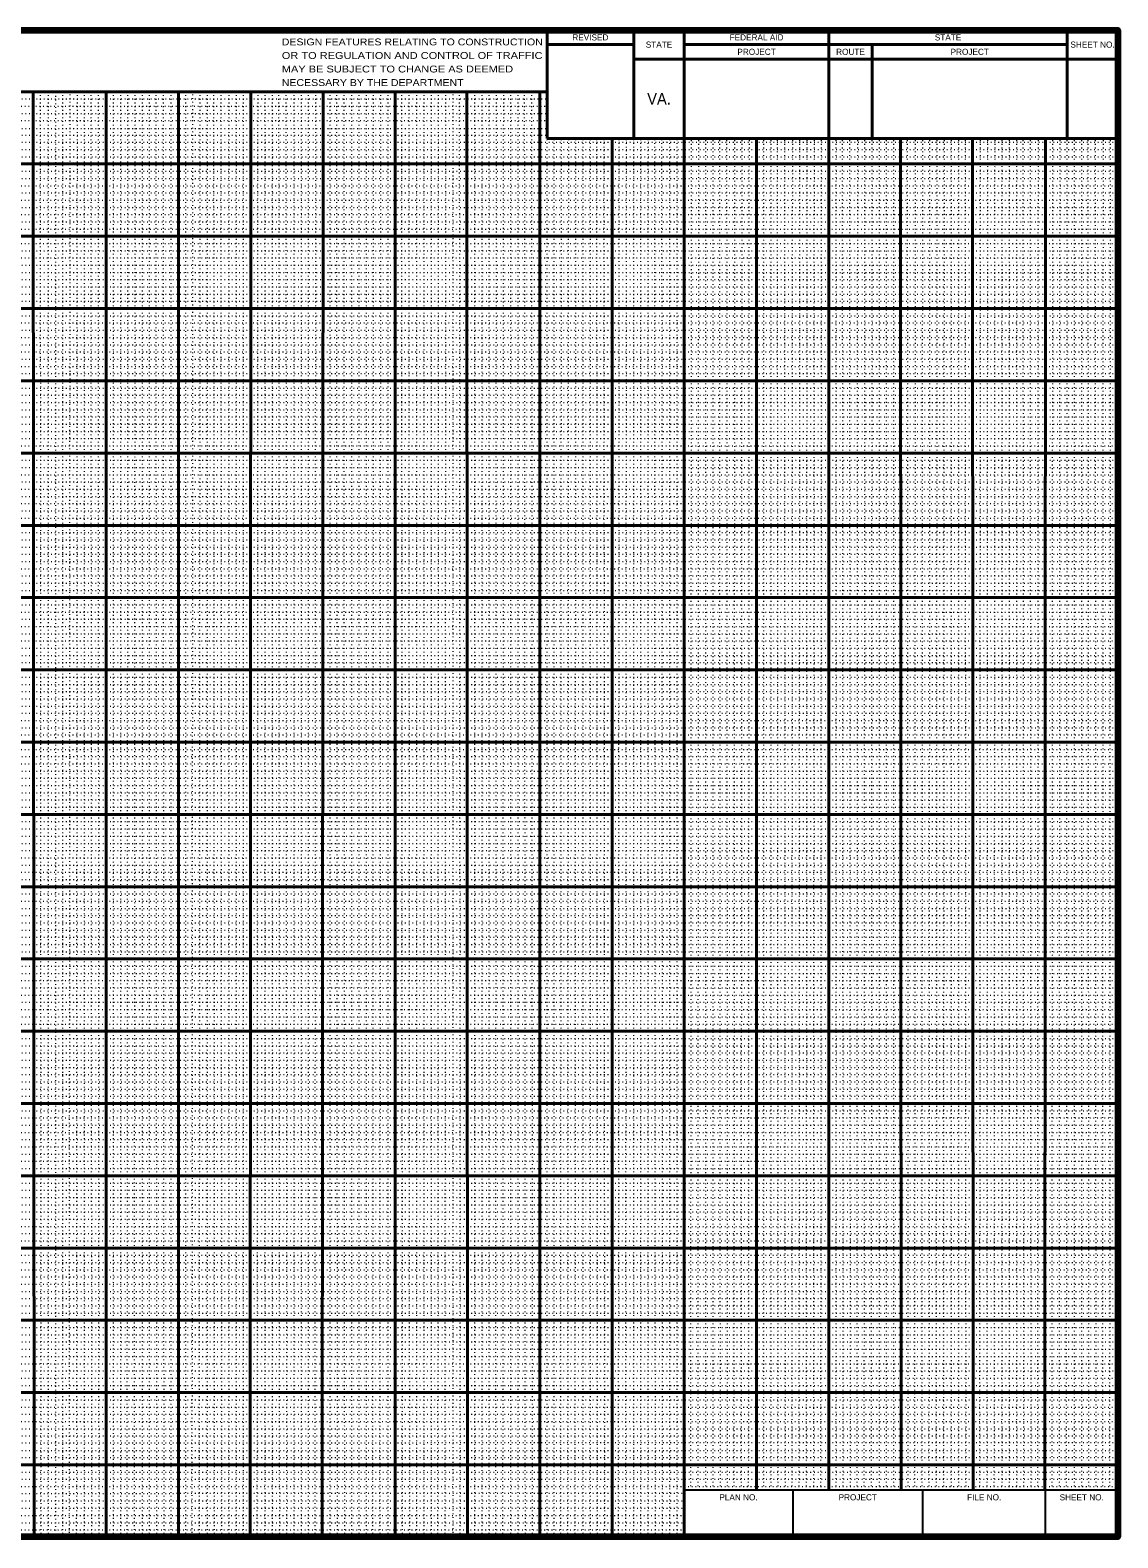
# Model space of a CAD drawing. Extents: x 224728 to 225078, y 224738 to 270738.
# Drawn here: x 224917.8 to 225068.4, y 241768.3 to 241976.9 of the extents above; entities that cross this region are included whole.
import ezdxf
from ezdxf.enums import TextEntityAlignment as Align

# ---------------------------------------------------------------- set-up
doc = ezdxf.new("R2010")
doc.units = 0
doc.header["$LTSCALE"] = 0.34
doc.linetypes.add('DOTTED', pattern=[1.5, 0.3, -1.2])
for name, color, linetype, lineweight in [('59', 7, 'DOTTED', 13), ('60', 7, 'Continuous', 40), ('61', 7, 'Continuous', 40)]:
    doc.layers.add(name, color=color, linetype=linetype, lineweight=lineweight)

msp = doc.modelspace()

# ---------------------------------------------------------------- linework, layer by layer
at = {"layer": '59'}
for p, q in [((224919.3649, 241768.3648), (224919.2649, 241968.3648)), ((224920.3649, 241768.3648), (224920.3649, 241968.3648)), ((224921.3649, 241768.2648), (224921.3649, 241968.3648)), ((224922.3649, 241768.3648), (224922.3649, 241968.3648)), ((224923.2649, 241768.4648), (224923.3649, 241968.3648)), ((224924.2649, 241768.3648), (224924.3649, 241968.3648)), ((224925.3649, 241768.3648), (224925.3649, 241968.3648)), ((224926.3649, 241768.3648), (224926.2649, 241968.3648)), ((224927.3649, 241768.3648), (224927.2649, 241968.3648)), ((224929.3649, 241768.3648), (224929.3649, 241968.3648)), ((224930.3649, 241768.3648), (224930.3649, 241968.3648)), ((224931.2649, 241768.3648), (224931.3649, 241968.3648)), ((224932.2649, 241768.3648), (224932.3649, 241968.3648)), ((224933.3649, 241768.3648), (224933.3649, 241968.3648)), ((224934.3649, 241768.3648), (224934.3649, 241968.3648)), ((224935.3649, 241768.3648), (224935.2649, 241968.3648)), ((224936.3649, 241768.3648), (224936.2649, 241968.3648)), ((224937.3649, 241768.3648), (224937.3649, 241968.3648)), ((224939.3649, 241768.3648), (224939.3649, 241968.4648)), ((224940.2649, 241768.4648), (224940.3649, 241968.3648)), ((224941.2649, 241768.3648), (224941.3649, 241968.3648)), ((224942.3649, 241768.3648), (224942.3649, 241968.3648)), ((224943.3649, 241768.3648), (224943.2649, 241968.3648)), ((224944.3649, 241768.3648), (224944.2649, 241968.3648)), ((224945.3649, 241768.3648), (224945.3649, 241968.3648)), ((224946.3649, 241768.3648), (224946.3649, 241968.3648)), ((224947.3649, 241768.3648), (224947.3649, 241968.3648)), ((224949.2649, 241768.3648), (224949.3649, 241968.3648)), ((224950.3649, 241768.3648), (224950.3649, 241968.3648)), ((224951.3649, 241768.3648), (224951.3649, 241968.3648)), ((224952.3649, 241768.3648), (224952.2649, 241968.3648)), ((224953.3649, 241768.3648), (224953.2649, 241968.3648)), ((224954.3649, 241768.3648), (224954.3649, 241968.3648)), ((224955.3649, 241768.3648), (224955.3649, 241968.3648)), ((224956.3649, 241768.3648), (224956.3649, 241968.3648)), ((224957.2649, 241768.3648), (224957.3649, 241968.3648)), ((224959.3649, 241768.3648), (224959.3649, 241968.3648)), ((224960.3649, 241768.3648), (224960.2649, 241968.3648)), ((224961.3649, 241768.3648), (224961.2649, 241968.3648)), ((224962.3649, 241768.3648), (224962.3649, 241968.3648)), ((224963.3649, 241768.3648), (224963.3649, 241968.3648)), ((224964.3649, 241768.3648), (224964.3649, 241968.3648)), ((224965.2649, 241768.3648), (224965.3649, 241968.3648)), ((224966.2649, 241768.3648), (224966.3649, 241968.3648)), ((224967.3649, 241768.3648), (224967.3649, 241968.3648)), ((224969.3649, 241768.3648), (224969.2649, 241968.3648)), ((224970.3649, 241768.3648), (224970.2649, 241968.3648)), ((224971.3649, 241768.3648), (224971.3649, 241968.3648)), ((224972.3649, 241768.3648), (224972.3649, 241968.3648)), ((224973.3649, 241768.3648), (224973.3649, 241968.3648)), ((224974.2649, 241768.3648), (224974.3649, 241968.3648)), ((224975.2649, 241768.3648), (224975.3649, 241968.3648)), ((224976.3649, 241768.4648), (224976.3649, 241968.3648)), ((224977.3649, 241768.3648), (224977.2649, 241968.4648)), ((224979.3649, 241768.3648), (224979.3649, 241968.3648)), ((224980.3649, 241768.3648), (224980.3649, 241968.3648)), ((224981.3649, 241768.3648), (224981.3649, 241968.3648)), ((224982.2649, 241768.3648), (224982.3649, 241968.3648)), ((224983.2649, 241768.3648), (224983.3649, 241968.3648)), ((224984.3649, 241768.3648), (224984.3649, 241968.3648)), ((224985.3649, 241768.3648), (224985.3649, 241968.3648)), ((224986.3649, 241768.3648), (224986.2649, 241968.3648)), ((224987.3649, 241768.3648), (224987.2649, 241968.3648)), ((224748.2649, 241966.3648), (224989.3649, 241966.3648)), ((224748.3649, 241967.3648), (224989.3649, 241967.3648)), ((224748.2649, 241964.3648), (224989.3649, 241964.3648)), ((224748.3649, 241965.3648), (224989.3649, 241965.3648)), ((224748.3649, 241963.3648), (224989.3649, 241963.2648)), ((224748.3649, 241962.3648), (224989.3649, 241962.3648)), ((224989.3649, 241768.3648), (224989.3649, 241961.8844)), ((224990.3649, 241768.3648), (224990.3649, 241961.8844)), ((224991.2649, 241768.3648), (224991.3647, 241961.8844)), ((224992.2649, 241768.3648), (224992.3647, 241961.8844)), ((224993.2649, 241768.3648), (224993.3647, 241961.8844)), ((224994.3649, 241768.3648), (224994.3649, 241961.8844)), ((224995.3649, 241768.3648), (224995.3649, 241961.8844)), ((224996.3649, 241768.3648), (224996.2651, 241961.8844)), ((224997.3649, 241768.3648), (224997.2651, 241961.8844)), ((224999.2649, 241768.3648), (224999.3647, 241961.8844)), ((225000.2649, 241768.3648), (225000.3647, 241961.8844)), ((225001.3649, 241768.3648), (225001.3649, 241961.8844)), ((225002.3649, 241768.3648), (225002.3649, 241961.8844)), ((225003.3649, 241768.3648), (225003.3649, 241961.8844)), ((225004.3649, 241768.3648), (225004.2652, 241961.8844)), ((225005.3649, 241768.3648), (225005.2651, 241961.8844)), ((225006.3649, 241768.3648), (225006.3649, 241961.8844)), ((225007.3649, 241768.3648), (225007.3649, 241961.8844)), ((225009.2683, 241774.885), (225009.3646, 241961.8845)), ((225010.2683, 241774.885), (225010.3646, 241961.8845)), ((225011.3648, 241774.885), (225011.3648, 241961.8845)), ((225012.3648, 241774.885), (225012.3648, 241961.8845)), ((225013.3614, 241774.885), (225013.2651, 241961.8845)), ((225014.3614, 241774.885), (225014.2651, 241961.8845)), ((225015.2683, 241774.885), (225015.3646, 241961.8845)), ((225016.2683, 241774.885), (225016.3646, 241961.8845)), ((225017.2683, 241774.885), (225017.3646, 241961.8845)), ((225019.3648, 241774.885), (225019.3648, 241961.8845)), ((225020.3648, 241774.885), (225020.3648, 241961.8845)), ((225021.3614, 241774.885), (225021.2651, 241961.8845)), ((225022.3614, 241774.885), (225022.2651, 241961.8845)), ((225023.2683, 241774.885), (225023.3646, 241961.8845)), ((225024.2683, 241774.885), (225024.3646, 241961.8845)), ((225025.2683, 241774.885), (225025.3646, 241961.8845)), ((225026.2683, 241774.885), (225026.3646, 241961.8845)), ((225027.2683, 241774.885), (225027.3646, 241961.8845)), ((225029.3648, 241774.885), (225029.3648, 241961.8845)), ((225030.3614, 241774.885), (225030.2651, 241961.8845)), ((225031.3614, 241774.885), (225031.2651, 241961.8845)), ((225032.2683, 241774.885), (225032.3646, 241961.8845)), ((225033.2683, 241774.885), (225033.3646, 241961.8845)), ((225034.2683, 241774.885), (225034.3646, 241961.8845)), ((225035.3648, 241774.885), (225035.3648, 241961.8846)), ((225036.3648, 241774.885), (225036.3648, 241961.8846)), ((225037.3648, 241774.885), (225037.3648, 241961.8846)), ((225039.3614, 241774.885), (225039.2651, 241961.8846)), ((225040.2682, 241774.885), (225040.3645, 241961.8846)), ((225041.2683, 241774.885), (225041.3646, 241961.8846)), ((225042.2683, 241774.885), (225042.3646, 241961.8846)), ((225043.2683, 241774.885), (225043.3646, 241961.8845)), ((225044.2683, 241774.885), (225044.3646, 241961.8845)), ((225045.3648, 241774.885), (225045.3648, 241961.8845)), ((225046.3648, 241774.885), (225046.3648, 241961.8845)), ((225047.3614, 241774.885), (225047.2651, 241961.8845)), ((225049.2683, 241774.885), (225049.3646, 241961.8845)), ((225050.2682, 241774.885), (225050.3646, 241961.8845)), ((225051.2683, 241774.885), (225051.3646, 241961.8845)), ((225052.3648, 241774.885), (225052.3648, 241961.8845)), ((225053.3648, 241774.885), (225053.3648, 241961.8845)), ((225054.3648, 241774.885), (225054.3648, 241961.8845)), ((225055.3614, 241774.885), (225055.2651, 241961.8845)), ((225056.3614, 241774.885), (225056.2651, 241961.8845)), ((225057.2682, 241774.885), (225057.3645, 241961.8845)), ((225059.2683, 241774.885), (225059.3646, 241961.8845)), ((225060.2683, 241774.885), (225060.3646, 241961.8845)), ((225061.2683, 241774.885), (225061.3646, 241961.8845)), ((225062.3648, 241774.885), (225062.3648, 241961.8845)), ((225063.3648, 241774.885), (225063.3648, 241961.8845)), ((225064.3614, 241774.885), (225064.2651, 241961.8845)), ((225065.3614, 241774.885), (225065.2651, 241961.8845)), ((225066.2683, 241774.885), (225066.3646, 241961.8845)), ((225067.2682, 241774.885), (225067.3646, 241961.8845)), ((224748.3649, 241961.3648), (225068.2649, 241961.3648)), ((224748.3649, 241960.3648), (225068.3649, 241960.3648)), ((224748.3649, 241959.3648), (225068.3649, 241959.3648)), ((224748.3649, 241957.3648), (225068.3649, 241957.3648)), ((224748.3649, 241956.3648), (225068.3649, 241956.3648)), ((224748.2649, 241955.3648), (225068.3649, 241955.3648)), ((224748.3649, 241954.3648), (225068.3649, 241954.3648)), ((224748.2649, 241953.3648), (225068.3649, 241953.3648)), ((224748.2649, 241951.3648), (225068.3649, 241951.3648)), ((224748.3649, 241952.3648), (225068.2649, 241952.3648)), ((224748.2649, 241949.3648), (225068.3649, 241949.3648)), ((224748.3649, 241950.3648), (225068.3649, 241950.3648)), ((224748.2649, 241947.3648), (225068.3649, 241947.3648)), ((224748.2649, 241945.3648), (225068.3649, 241945.3648)), ((224748.3649, 241946.3648), (225068.2649, 241946.3648)), ((224748.3649, 241944.3648), (225068.2649, 241944.3648)), ((224748.3649, 241943.3648), (225068.3649, 241943.3648)), ((224748.3649, 241942.3648), (225068.3649, 241942.3648)), ((224748.3649, 241941.3648), (225068.3649, 241941.3648)), ((224748.3649, 241940.3648), (225068.3649, 241940.3648)), ((224748.3649, 241939.3648), (225068.3649, 241939.3648)), ((224748.3649, 241937.3648), (225068.3649, 241937.3648)), ((224748.2649, 241936.3648), (225068.3649, 241936.3648)), ((224748.3649, 241935.3648), (225068.2649, 241935.3648)), ((224748.2649, 241934.3648), (225068.3649, 241934.3648)), ((224748.3649, 241933.3648), (225068.3649, 241933.3648)), ((224748.2649, 241932.3648), (225068.3649, 241932.3648)), ((224748.3649, 241931.3648), (225068.2649, 241931.3648)), ((224748.2649, 241930.3648), (225068.3649, 241930.3648)), ((224748.3649, 241929.3648), (225068.2649, 241929.3648)), ((224748.3649, 241927.3648), (225068.2649, 241927.3648)), ((224748.3649, 241926.3648), (225068.3649, 241926.3648)), ((224748.3649, 241925.3648), (225068.2649, 241925.3648)), ((224748.3649, 241924.3648), (225068.3649, 241924.3648)), ((224748.3649, 241923.3648), (225068.3649, 241923.3648)), ((224748.3649, 241922.3648), (225068.3649, 241922.3648)), ((224748.3649, 241921.3648), (225068.3649, 241921.3648)), ((224748.3649, 241920.3648), (225068.3649, 241920.3648)), ((224748.2649, 241919.3648), (225068.3649, 241919.3648)), ((224748.3649, 241917.3648), (225068.3649, 241917.3648)), ((224748.3649, 241916.3648), (225068.3649, 241916.3648)), ((224748.2649, 241915.3648), (225068.3649, 241915.3648)), ((224748.3649, 241914.3648), (225068.2649, 241914.3648)), ((224748.2649, 241913.3648), (225068.3649, 241913.3648)), ((224748.3649, 241912.3648), (225068.2649, 241912.3648)), ((224748.2649, 241911.3648), (225068.3649, 241911.3648)), ((224748.3649, 241910.3648), (225068.2649, 241910.3648)), ((224748.2649, 241909.3648), (225068.3649, 241909.3648)), ((224748.3649, 241907.3648), (225068.3649, 241907.3648)), ((224748.3649, 241906.3648), (225068.3649, 241906.3648)), ((224748.3649, 241905.3648), (225068.3649, 241905.3648)), ((224748.3649, 241904.3648), (225068.3649, 241904.3648)), ((224748.3649, 241903.3648), (225068.3649, 241903.3648)), ((224748.2649, 241902.3648), (225068.3649, 241902.3648)), ((224748.3649, 241901.3648), (225068.3649, 241901.3648)), ((224748.3649, 241900.3648), (225068.3649, 241900.3648)), ((224748.3649, 241899.3648), (225068.3649, 241899.3648)), ((224748.3649, 241897.3648), (225068.2649, 241897.3648)), ((224748.2649, 241896.3648), (225068.3649, 241896.3648)), ((224748.3649, 241895.3648), (225068.2649, 241895.3648)), ((224748.2649, 241894.3648), (225068.3649, 241894.3648)), ((224748.3649, 241893.3648), (225068.2649, 241893.3648)), ((224748.2649, 241892.3648), (225068.3649, 241892.3648)), ((224748.3649, 241891.3648), (225068.2649, 241891.3648)), ((224748.3649, 241890.3648), (225068.3649, 241890.3648)), ((224748.3649, 241889.3648), (225068.2649, 241889.3648)), ((224748.3649, 241887.3648), (225068.3649, 241887.3648)), ((224748.3649, 241886.3648), (225068.3649, 241886.3648)), ((224748.3649, 241885.3648), (225068.3649, 241885.3648)), ((224748.3649, 241884.3648), (225068.3649, 241884.3648)), ((224748.3649, 241883.3648), (225068.3649, 241883.3648)), ((224748.2649, 241881.3648), (225068.3649, 241881.3648)), ((224748.3649, 241882.3648), (225068.3649, 241882.3648)), ((224748.2649, 241879.3648), (225068.3649, 241879.3648)), ((224748.3649, 241880.3648), (225068.3649, 241880.3648)), ((224748.2649, 241877.3648), (225068.3649, 241877.3648)), ((224748.3649, 241876.3648), (225068.2649, 241876.3648)), ((224748.2649, 241875.3648), (225068.3649, 241875.3648)), ((224748.3649, 241874.3648), (225068.2649, 241874.3648)), ((224748.3649, 241873.3648), (225068.3649, 241873.3648)), ((224748.3649, 241872.3648), (225068.2649, 241872.3648)), ((224748.3649, 241871.3648), (225068.3649, 241871.3648)), ((224748.3649, 241870.3648), (225068.3649, 241870.3648)), ((224748.3649, 241869.3648), (225068.3649, 241869.3648)), ((224748.3649, 241867.3648), (225068.3649, 241867.3648)), ((224748.3649, 241866.3648), (225068.3649, 241866.3648)), ((224748.3649, 241865.3648), (225068.3649, 241865.3648)), ((224748.3649, 241864.3648), (225068.3649, 241864.3648)), ((224748.2649, 241862.3648), (225068.3649, 241862.3648)), ((224748.3649, 241863.3648), (225068.3649, 241863.3648)), ((224748.2649, 241860.3648), (225068.3649, 241860.3648)), ((224748.3649, 241861.3648), (225068.2649, 241861.3648)), ((224748.3649, 241859.3648), (225068.2649, 241859.3648)), ((224748.2649, 241856.3648), (225068.3649, 241856.3648)), ((224748.3649, 241857.3648), (225068.2649, 241857.3648)), ((224748.3649, 241855.3648), (225068.2649, 241855.3648)), ((224748.3649, 241854.3648), (225068.3649, 241854.3648)), ((224748.3649, 241853.3648), (225068.2649, 241853.3648)), ((224748.3649, 241852.3648), (225068.3649, 241852.3648)), ((224748.3649, 241851.3648), (225068.3649, 241851.3648)), ((224748.3649, 241850.3648), (225068.3649, 241850.3648)), ((224748.3649, 241849.3648), (225068.3649, 241849.3648)), ((224748.3649, 241847.3648), (225068.3649, 241847.3648)), ((224748.2649, 241845.3648), (225068.3649, 241845.3648)), ((224748.3649, 241846.3648), (225068.3649, 241846.3648)), ((224748.2649, 241843.3648), (225068.3649, 241843.3648)), ((224748.3649, 241844.3648), (225068.2649, 241844.3648)), ((224748.2649, 241841.3648), (225068.3649, 241841.3648)), ((224748.3649, 241842.3648), (225068.2649, 241842.3648)), ((224748.2649, 241839.3648), (225068.3649, 241839.3648)), ((224748.3649, 241840.3648), (225068.2649, 241840.3648)), ((224748.3649, 241837.3648), (225068.3649, 241837.3648)), ((224748.3649, 241836.3648), (225068.2649, 241836.3648)), ((224748.3649, 241835.3648), (225068.3649, 241835.3648)), ((224748.3649, 241834.3648), (225068.3649, 241834.3648)), ((224748.3649, 241833.3648), (225068.3649, 241833.3648)), ((224748.3649, 241832.3648), (225068.3649, 241832.3648)), ((224748.3649, 241831.3648), (225068.3649, 241831.3648)), ((224748.3649, 241830.3648), (225068.3649, 241830.3648)), ((224748.3649, 241829.3648), (225068.3649, 241829.3648)), ((224748.2649, 241826.3648), (225068.3649, 241826.3648)), ((224748.3649, 241827.3648), (225068.2649, 241827.3648)), ((224748.2649, 241824.3648), (225068.3649, 241824.3648)), ((224748.3649, 241825.3648), (225068.2649, 241825.3648)), ((224748.2649, 241822.3648), (225068.3649, 241822.3648)), ((224748.3649, 241823.3648), (225068.2649, 241823.3648)), ((224748.2649, 241820.3648), (225068.3649, 241820.3648)), ((224748.3649, 241821.3648), (225068.2649, 241821.3648)), ((224748.3649, 241819.3648), (225068.2649, 241819.3648)), ((224748.3649, 241817.3648), (225068.2649, 241817.3648)), ((224748.3649, 241816.3648), (225068.3649, 241816.3648)), ((224748.3649, 241815.3648), (225068.3649, 241815.3648)), ((224748.3649, 241814.3648), (225068.3649, 241814.3648)), ((224748.3649, 241813.3648), (225068.3649, 241813.3648)), ((224748.3649, 241812.3648), (225068.3649, 241812.3648)), ((224748.2649, 241811.3648), (225068.3649, 241811.3648)), ((224748.3649, 241810.3648), (225068.3649, 241810.3648)), ((224748.2649, 241809.3648), (225068.3649, 241809.3648)), ((224748.2649, 241807.3648), (225068.3649, 241807.3648)), ((224748.2649, 241805.3648), (225068.3649, 241805.3648)), ((224748.3649, 241806.3648), (225068.2649, 241806.3648)), ((224748.2649, 241803.3648), (225068.3649, 241803.3648)), ((224748.3649, 241804.3648), (225068.2649, 241804.3648)), ((224748.3649, 241802.3648), (225068.2649, 241802.3648)), ((224748.3649, 241801.3648), (225068.3649, 241801.3648)), ((224748.3649, 241800.3648), (225068.2649, 241800.3648)), ((224748.3649, 241799.3648), (225068.3649, 241799.3648)), ((224748.3649, 241797.3648), (225068.3649, 241797.3648)), ((224748.3649, 241796.3648), (225068.3649, 241796.3648)), ((224748.3649, 241795.3648), (225068.3649, 241795.3648)), ((224748.3649, 241794.3648), (225068.3649, 241794.3648)), ((224748.3649, 241793.3648), (225068.3649, 241793.3648)), ((224748.2649, 241792.3648), (225068.3649, 241792.3648)), ((224748.3649, 241791.3648), (225068.2649, 241791.3648)), ((224748.2649, 241790.3648), (225068.3649, 241790.3648)), ((224748.3649, 241789.3648), (225068.3649, 241789.3648)), ((224748.3649, 241787.3648), (225068.2649, 241787.3648)), ((224748.2649, 241786.3648), (225068.3649, 241786.3648)), ((224748.3649, 241785.3648), (225068.2649, 241785.3648)), ((224748.2649, 241784.3648), (225068.3649, 241784.3648)), ((224748.3649, 241783.3648), (225068.2649, 241783.3648)), ((224748.3649, 241782.3648), (225068.3649, 241782.3648)), ((224748.3649, 241781.3648), (225068.2649, 241781.4648)), ((224748.3649, 241780.3648), (225068.3649, 241780.3648)), ((224748.3649, 241779.3648), (225068.3649, 241779.3648)), ((224748.3649, 241777.3648), (225068.3649, 241777.3648)), ((224748.3649, 241776.3648), (225068.3649, 241776.3648)), ((224748.2649, 241775.3648), (225068.3649, 241775.3648)), ((224748.3649, 241774.3648), (225008.3649, 241774.4461)), ((224748.3649, 241773.3648), (225008.3649, 241773.3648)), ((224748.3649, 241772.3648), (225008.3649, 241772.3648)), ((224748.2649, 241771.3648), (225008.3649, 241771.3648)), ((224748.3649, 241770.3648), (225008.3649, 241770.3648)), ((224748.2649, 241769.3648), (225008.3649, 241769.3648))]:
    msp.add_line(p, q, dxfattribs=at)
at = {"layer": '60'}
for p, q in [((224748.2649, 241968.3648), (224989.3649, 241968.3648)), ((224918.3649, 241768.3648), (224918.2649, 241968.3648)), ((224928.3649, 241768.3648), (224928.3649, 241968.3648)), ((224938.3649, 241768.3648), (224938.3649, 241968.3648)), ((224948.2649, 241768.3648), (224948.3649, 241968.3648)), ((224958.2649, 241768.3648), (224958.3649, 241968.3648)), ((224968.3649, 241768.3648), (224968.3649, 241968.3648)), ((224978.3649, 241768.3648), (224978.2649, 241968.3648)), ((224988.3649, 241768.3648), (224988.3649, 241968.3648)), ((224998.3649, 241768.3648), (224998.3649, 241961.8844)), ((225018.3648, 241774.885), (225018.3648, 241961.8845)), ((225028.3648, 241774.885), (225028.3648, 241961.8845)), ((225038.3614, 241774.885), (225038.2651, 241961.8846)), ((225048.3614, 241774.885), (225048.2651, 241961.8845)), ((225058.2682, 241774.885), (225058.3646, 241961.8845)), ((224748.3649, 241958.3648), (225068.3649, 241958.3648)), ((224748.3649, 241948.3648), (225068.2649, 241948.3648)), ((224748.3649, 241938.3648), (225068.3649, 241938.3648)), ((224748.2649, 241928.3648), (225068.3649, 241928.3648)), ((224748.3649, 241918.3648), (225068.2649, 241918.3648)), ((224748.3649, 241908.3648), (225068.2649, 241908.3648)), ((224748.2649, 241898.3648), (225068.3649, 241898.3648)), ((224748.3649, 241888.3648), (225068.3649, 241888.3648)), ((224748.3649, 241878.3648), (225068.2649, 241878.3648)), ((224748.3649, 241868.3648), (225068.3649, 241868.3648)), ((224748.2649, 241858.3648), (225068.3649, 241858.3648)), ((224748.3649, 241848.3648), (225068.3649, 241848.3648)), ((224748.3649, 241838.3648), (225068.2649, 241838.3648)), ((224748.2649, 241828.3648), (225068.3649, 241828.3648)), ((224748.3649, 241818.3648), (225068.3649, 241818.3648)), ((224748.3649, 241808.3648), (225068.2649, 241808.3648)), ((224748.3649, 241798.3648), (225068.3649, 241798.3648)), ((224748.2649, 241788.3648), (225068.3649, 241788.3648)), ((224748.3649, 241778.3648), (225068.3649, 241778.3648))]:
    msp.add_line(p, q, dxfattribs=at)
msp.add_lwpolyline([(225008.3648, 241768.3849), (225008.3648, 241774.885), (225008.3648, 241961.8845)], dxfattribs=at)
at = {"layer": '61'}
for p, q in [((224989.362, 241976.8849), (224989.362, 241961.8845)), ((225001.3624, 241961.8845), (225001.3624, 241976.8849)), ((225008.3628, 241961.8845), (225008.3628, 241976.8849)), ((225028.3636, 241961.8845), (225028.3632, 241976.8849)), ((225061.3644, 241961.8845), (225061.3644, 241976.8849)), ((224989.362, 241974.8849), (225001.3624, 241974.8849)), ((225008.3628, 241974.8849), (225061.3644, 241974.8849)), ((225034.3636, 241961.8845), (225034.3636, 241974.8849)), ((224989.362, 241961.8845), (225001.3624, 241961.8845)), ((225001.3624, 241961.8845), (225068.3644, 241961.8845))]:
    msp.add_line(p, q, dxfattribs=at)
at = {"layer": '61', "lineweight": 25}
for p, q in [((225068.3652, 241774.8849), (225008.3632, 241774.8849)), ((225008.3632, 241774.8849), (225008.3632, 241768.3849)), ((225023.3636, 241774.8849), (225023.3636, 241768.3849)), ((225041.3644, 241768.3849), (225041.364, 241774.8849)), ((225058.3648, 241768.3849), (225058.3648, 241774.8849))]:
    msp.add_line(p, q, dxfattribs=at)
at = {"layer": '61', "lineweight": 158}
msp.add_lwpolyline([(225068.3648, 241774.885), (225068.3648, 241768.3849), (224748.3648, 241768.3849), (224748.3648, 241976.8849), (225068.3648, 241976.8849)], close=True, dxfattribs=at)
at = {"layer": '61'}
msp.add_lwpolyline([(225001.3624, 241972.8849), (225008.3628, 241972.8849), (225068.3648, 241972.8849)], dxfattribs=at)

# ---------------------------------------------------------------- texts
for s, width, p in [('DESIGN FEATURES RELATING TO CONSTRUCTION', 1.15, (224952.6556, 241974.7782)), ('OR TO REGULATION AND CONTROL OF TRAFFIC', 1.2, (224952.6556, 241972.903)), ('NECESSARY BY THE DEPARTMENT', 1.15, (224952.6556, 241969.1583)), ('MAY BE SUBJECT TO CHANGE AS DEEMED', 1.2, (224952.6556, 241971.0307))]:
    msp.add_text(s, height=0.95, dxfattribs=dict(at, width=width)).set_placement(p)
for s, p in [('REVISED', (224995.3622, 241975.4599)), ('STATE', (225004.8626, 241974.4599)), ('FEDERAL AID', (225018.363, 241975.46)), ('PROJECT', (225018.3631, 241973.46)), ('ROUTE', (225031.3635, 241973.4599)), ('STATE', (225044.8638, 241975.4599)), ('PROJECT', (225047.8641, 241973.4599)), ('SHEET NO.', (225064.8646, 241974.4599)), ('PLAN NO.', (225015.8634, 241773.4536)), ('PROJECT', (225032.3639, 241773.4536)), ('FILE NO.', (225049.8645, 241773.4536)), ('SHEET NO.', (225063.3648, 241773.4536))]:
    msp.add_text(s, height=0.85, dxfattribs=at).set_placement(p, align=Align.CENTER)
at = {"layer": '61', "width": 0.95}
msp.add_text('VA.', height=1.6, dxfattribs=at).set_placement((225004.8626, 241966.5847), align=Align.CENTER)

doc.saveas('drawing.dxf')
